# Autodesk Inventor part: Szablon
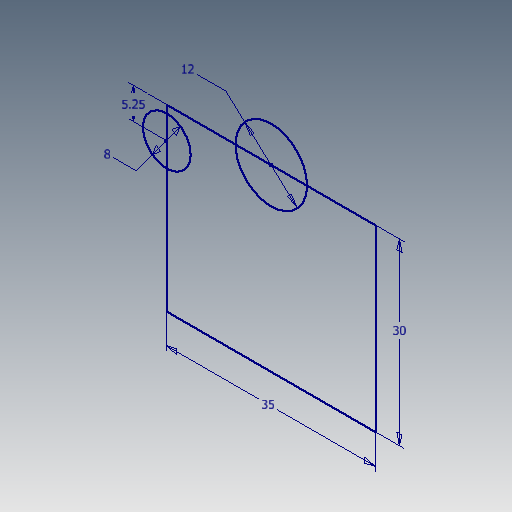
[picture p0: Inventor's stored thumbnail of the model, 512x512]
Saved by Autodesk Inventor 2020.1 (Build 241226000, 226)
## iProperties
Created: 2005-10
Part Number: Szablon
Document SubType Name: Modeling
Designer: F.Stasiak
Stock Number: Szablon
Density: 1 g/cm^3
Material: Ogólny
Appearance: Domyślna
Manager: www.cadconsulting.pl
Company: Fabian Stasiak CAD Consulting
Author: F.Stasiak
Subject: Zbiór ćwiczeń. Autodesk Inventor 2020. Kurs podstawowy
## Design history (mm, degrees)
sketch "Szkic1"
  geometry: L1 (17.5, 0)-(-17.5, 0); L2 (-17.5, 0)-(-17.5, -30); L3 (-17.5, -30)-(17.5, -30); L4 (17.5, -30)-(17.5, 0); C1 r 6 at (0, 0); C2 r 4 at (-17.5, -5.25); 2 further points
  constraints: 8 end point, 2 centre point, 2 coincident, 2 parallel, 1 horizontal, 1 midpoint, 1 perpendicular, 1 point on line
  dimensions: "d0" = 12 diameter of C1; "d4" = 35 distance of L2.end L3.end; "d5" = 30 distance of L3.end L1.start; "d6" = 8 diameter of C2; "d7" = 5.25 vertical distance of C1.centre C2.centre
node "Płaszczyzna konstrukcyjna1"
node "Korpusy bryłowe"
node "Korpusy powierzchniowe"
other parameters: "d8" = 0
